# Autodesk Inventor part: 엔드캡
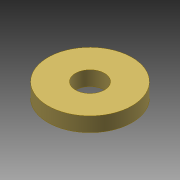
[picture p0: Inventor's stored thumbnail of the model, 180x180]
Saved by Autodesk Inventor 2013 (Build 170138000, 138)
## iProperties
Created: 2023-03
Part Number: 엔드캡
Material: 강철, 연강
Document SubType Name: Modeling
Designer: mdu-01
Density: 1 g/cm^3
Author: mdu-01
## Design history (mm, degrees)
sketch "스케치1"
  geometry: C1 r 13 at (0, 0); 1 further point
  constraints: 1 centre point, 1 coincident
  dimensions: "d0" = 26 diameter of C1
extrude "돌출1" new body sketch "스케치1" distance "d1" = 4.5; taper "d2" = 0 deg
hole "구멍1" diameter "d6" = 9; stored, may be unused: countersink angle "d10" = 90 deg, drill point angle "d12" = 118 deg; dims "d4" = 10, "d5" = 10, "d7" = 6, "d8" = 17.3, "d9" = 2, "d11" = 8
node "솔리드1"
